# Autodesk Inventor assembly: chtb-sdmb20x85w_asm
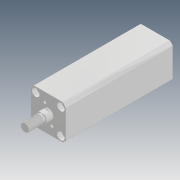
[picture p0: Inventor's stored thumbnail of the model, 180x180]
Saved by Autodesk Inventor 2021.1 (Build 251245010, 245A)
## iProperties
Company: Microsoft
Created: 2018-05
Part Number: chtb-sdmb20x85w_asm
Description: STEP AP214
Document SubType Name: Assembly
Designer: user
Title: chtb-sdmb20x85w_asm.STEP
Author: Windows
Revision Number: ÈÎºÎ
Sending System: SolidWorks 2015
Preprocessor: SwSTEP 2.0
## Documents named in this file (4)
- D:\Vault_2016\Projekty\Clamptek\Hydraulic\CHTB\CHTB-20\Inventor\CHTB-SDMB20x85W\chtb-sdmb20x85w_asm.iam
- D:\Vault_2016\Projekty\Clamptek\Hydraulic\CHTB\CHTB-20\Inventor\CHTB-SDMB20x85W\CHTB-SDMB20X85NBT.ipt
- D:\Vault_2016\Projekty\Clamptek\Hydraulic\CHTB\CHTB-20\Inventor\CHTB-SDMB20x85W\CHTB-SDMB20X85WHSG.ipt
- D:\Vault_2016\Projekty\Clamptek\Hydraulic\CHTB\CHTB-20\Inventor\CHTB-SDMB20x85W\QG_3.ipt
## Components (3 placed, 3 different names)
1. CHTB-SDMB20X85NBT_1
2. CHTB-SDMB20X85WHSG_2
3. QG_3_3
